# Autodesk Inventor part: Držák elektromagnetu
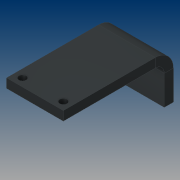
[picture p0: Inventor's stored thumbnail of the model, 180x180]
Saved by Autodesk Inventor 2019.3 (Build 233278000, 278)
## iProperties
Created: 2019-04
Part Number: Držák elektromagnetu
Material: Ocel, měkká, svařovaná
Document SubType Name: Plech
Designer: B-hon
Density: 7.85 g/cm^3
Sheet Metal Rule: Výchozí_mm
Appearance: Železo – šedé
Author: B-hon
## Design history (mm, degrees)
node "Plocha1"
  sketch "Náčrt1"
    geometry: L1 (0, 0)-(50, 0); L2 (50, 0)-(50, 26); L3 (50, 26)-(0, 26); L4 (0, 26)-(0, 0)
    constraints: 8 end point, 2 parallel, 1 horizontal, 1 perpendicular
    dimensions: "d0" = 50 distance of L3.end L2.end; "d1" = 26 distance of L2.end L1.end
node "Obruba1"
sketch "Náčrt3"
  geometry: L1 (50, 0)-(0, 0) reference; L2 (50, 0)-(50, -81) reference; L3 (0, 0)-(0, -81) reference; 3 further points
  constraints: 1 horizontal alignment
  dimensions: "d13" = 7 distance from line of L1 point (43, -7) (= d15); "d14" = 7 distance from line of L2 point (43, -7) (= d15); "d15" = 7 distance from line of L3 point (7, -7)
hole "Díra1" sketch "Náčrt3" at (7, -7), (43, -7) diameter "d16" = 6.5; stored, may be unused: countersink angle "d20" = 90 deg, drill point angle "d22" = 118 deg; dims "d17" = 6, "d18" = 4, "d19" = 2, "d21" = 8 (= Tloušťka)
node "Těleso1"
feature "Deska1" dims "d2" = 8 (= Tloušťka)
sketch "Náčrt2"
  geometry: L1 through (-25, 0) direction (1, 0); L2 through (0, 40.5) direction (0, 1); L3 (0, 81)-(-50, 81); L4 (-50, 81)-(-50, 0)
  constraints: 6 end point, 1 horizontal, 1 perpendicular, 1 vertical
feature "Deska2" dims "d2" = 8 (= Tloušťka), "d3" = 8 (= ŠířkaVýštipu), "d4" = 4 (= HloubkaVýštipu), "d5" = 16 (= MinimálníZbytek), "d6" = 8 (= PřechodovýPoloměr), "d7" = 97, "d8" = 90 deg, "d9" = 8 (= PoloměrOhybu), "d10" = 32 (= VelikostRohovéhoVýštipu), "d11" = 8 (= VelikostMezery), "d12" = 8 (= VelikostJacobihoPoloměru), "MezeraVystřižení" = 0.01
feature "Ohyb1" dims "d2" = 8 (= Tloušťka), "d3" = 8 (= ŠířkaVýštipu), "d4" = 4 (= HloubkaVýštipu), "d5" = 16 (= MinimálníZbytek), "d6" = 8 (= PřechodovýPoloměr), "d7" = 97, "d8" = 90 deg, "d9" = 8 (= PoloměrOhybu), "MezeraVystřižení" = 0.01
feature "Roh1" dims "d7" = 97, "d8" = 90 deg, "d10" = 32 (= VelikostRohovéhoVýštipu), "d11" = 8 (= VelikostMezery), "d12" = 8 (= VelikostJacobihoPoloměru)
other parameters: "Tloušťka" = 8 (derived), "KSoučinitel" = 4.4, "PoloměrOhybu" = 8 (= Tloušťka), "ŠířkaVýštipu" = 8 (= Tloušťka), "HloubkaVýštipu" = 4 (= 0.5 x Tloušťka), "VelikostRohovéhoVýštipu" = 32 (= 4 x Tloušťka), "MinimálníZbytek" = 16 (= 2 x Tloušťka), "PřechodovýPoloměr" = 8 (= PoloměrOhybu), "VelikostJacobihoPoloměru" = 8 (= PoloměrOhybu), "VelikostMezery" = 8 (= Tloušťka)
